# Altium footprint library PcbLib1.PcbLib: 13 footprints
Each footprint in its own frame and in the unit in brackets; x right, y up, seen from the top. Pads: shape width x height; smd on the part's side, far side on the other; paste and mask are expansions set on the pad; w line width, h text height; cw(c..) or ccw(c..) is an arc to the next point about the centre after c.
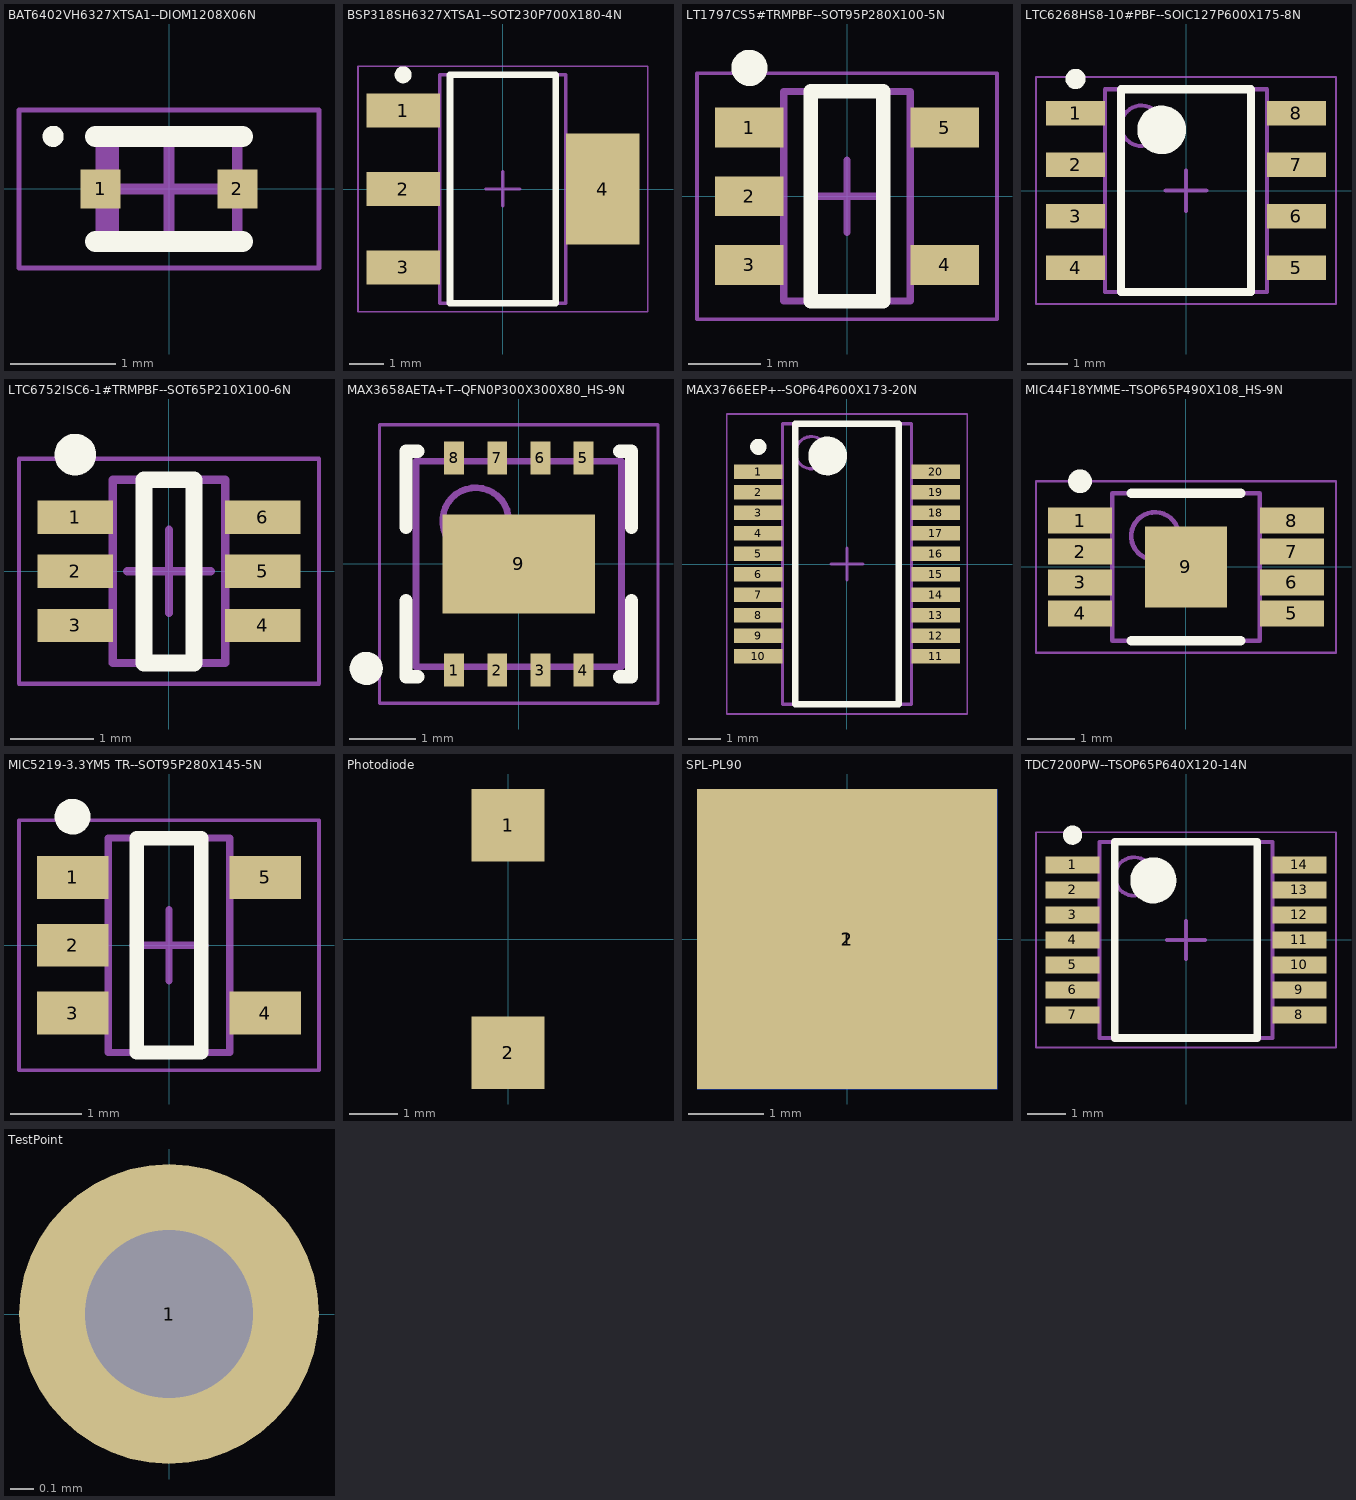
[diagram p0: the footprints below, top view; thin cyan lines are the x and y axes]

## BAT6402VH6327XTSA1--DIOM1208X06N [mm] "Molded Diode, 2-Leads, Body 1.20x0.80mm, IPC Medium Density"
height 0.59
pads (2):
  rect 0.38x0.37 smd: 1(-0.65,0) 2(0.65,0)
Top Overlay:
  circle w0.1: c-1.1,0.5 r0.05
  lines w0.2: -0.7,-0.5 0.7,-0.5 ; -0.7,0.5 0.7,0.5
Mechanical 13:
  rectangle: -0.65,-0.45 -0.475,0.45
  lines w0.1: -0.65,-0.45 0.65,-0.45 0.65,0.45 -0.65,0.45 -0.65,-0.45
Mechanical 15:
  lines w0.05: -1.425,-0.75 1.425,-0.75 1.425,0.75 -1.425,0.75 -1.425,-0.75
  lines w0.1: -0.45,0 0.45,0 ; 0,-0.45 0,0.45
3D body: height 0.59, standoff 0, extent -0.65,-0.45 0.65,0.45

## BSP318SH6327XTSA1--SOT230P700X180-4N [mm] "SOT223, 4-Leads, Body 6.50x7.00mm (avg), Pitch 2.30mm, IPC Medium Density"
height 1.8
pads (4):
  rect 2.15x1 smd: 1(-2.925,2.3) 2(-2.925,0) 3(-2.925,-2.3)
  rect 2.15x3.25 smd: 4(2.925,0)
Top Overlay:
  circle w0.25: c-2.925,3.35 r0.125
  lines w0.2: -1.55,-3.35 1.55,-3.35 1.55,3.35 -1.55,3.35 -1.55,-3.35
Mechanical 13:
  lines w0.1: -1.85,-3.35 1.85,-3.35 1.85,3.35 -1.85,3.35 -1.85,-3.35
Mechanical 15:
  lines w0.05: -4.25,-3.6 4.25,-3.6 4.25,3.6 -4.25,3.6 -4.25,-3.6
  lines w0.1: -0.5,0 0.5,0 ; 0,-0.5 0,0.5
3D body: height 1.8, standoff 0.02, extent -1.85,-3.35 1.85,3.35

## LT1797CS5#TRMPBF--SOT95P280X100-5N [mm] "SOT23, 5-Leads, Body 2.90x2.80mm, Pitch 0.95mm, IPC Medium Density"
height 1
pads (5):
  rect 0.95x0.55 smd: 1(-1.35,0.95) 2(-1.35,0) 3(-1.35,-0.95) 4(1.35,-0.95) 5(1.35,0.95)
Top Overlay:
  circle w0.25: c-1.35,1.775 r0.125
  lines w0.2: -0.5,-1.45 0.5,-1.45 0.5,1.45 -0.5,1.45 -0.5,-1.45
Mechanical 13:
  lines w0.1: -0.875,-1.45 -0.875,1.45 0.875,1.45 0.875,-1.45 -0.875,-1.45
Mechanical 15:
  lines w0.05: -2.075,-1.7 -2.075,1.7 2.075,1.7 2.075,-1.7 -2.075,-1.7
  lines w0.1: -0.5,0 0.5,0 ; 0,-0.5 0,0.5
3D body: height 1, standoff 0, extent -0.875,-1.45 0.875,1.45

## LTC6268HS8-10#PBF--SOIC127P600X175-8N [mm] "SOIC, 8-Leads, Body 4.90x3.90mm, Pitch 1.27mm, IPC Medium Density"
height 1.76
pads (8):
  rect 1.45x0.6 smd: 1(-2.725,1.905) 2(-2.725,0.635) 3(-2.725,-0.635) 4(-2.725,-1.905) 5(2.725,-1.905) 6(2.725,-0.635) 7(2.725,0.635) 8(2.725,1.905)
Top Overlay:
  circle w0.25: c-2.725,2.755 r0.125
  circle w0.6: c-0.6,1.5 r0.3
  lines w0.2: -1.6,-2.5 -1.6,2.5 1.6,2.5 1.6,-2.5 -1.6,-2.5
Mechanical 13:
  circle w0.1: c-1.1,1.6 r0.5
  lines w0.1: -2,-2.5 -2,2.5 2,2.5 2,-2.5 -2,-2.5
Mechanical 15:
  lines w0.05: -3.7,-2.8 -3.7,2.8 3.7,2.8 3.7,-2.8 -3.7,-2.8
  lines w0.1: -0.5,0 0.5,0 ; 0,-0.5 0,0.5
3D body: height 1.76, standoff 0.1, extent -2,-2.5 2,2.5

## LTC6752ISC6-1#TRMPBF--SOT65P210X100-6N [mm] "SOT23, 6-Leads, Body 2.00x2.10mm, Pitch 0.65mm, IPC Medium Density"
height 1
pads (6):
  rect 0.9x0.4 smd: 1(-1.125,0.65) 2(-1.125,0) 3(-1.125,-0.65) 4(1.125,-0.65) 5(1.125,0) 6(1.125,0.65)
Top Overlay:
  circle w0.25: c-1.125,1.4 r0.125
  lines w0.2: -0.3,-1.1 0.3,-1.1 0.3,1.1 -0.3,1.1 -0.3,-1.1
Mechanical 13:
  lines w0.1: -0.675,-1.1 -0.675,1.1 0.675,1.1 0.675,-1.1 -0.675,-1.1
Mechanical 15:
  lines w0.05: -1.8,-1.35 -1.8,1.35 1.8,1.35 1.8,-1.35 -1.8,-1.35
  lines w0.1: -0.5,0 0.5,0 ; 0,-0.5 0,0.5
3D body: height 1, standoff 0, extent -0.675,-1.1 0.675,1.1

## MAX3658AETA+T--QFN0P300X300X80_HS-9N [mm] "QFN, 8-Leads, Body 3.00x3.00mm, Pitch 0.65mm/0.00mm, Thermal Pad 2.30x1.50mm, IPC Medium Density"
height 0.8
pads (9):
  rect 0.3x0.5 smd: 1(-0.975,-1.6) 2(-0.325,-1.6) 3(0.325,-1.6) 4(0.975,-1.6) 5(0.975,1.6) 6(0.325,1.6) 7(-0.325,1.6) 8(-0.975,1.6)
  rect 2.3x1.5 smd: 9(0,0)
Top Overlay:
  circle w0.25: c-2.3,-1.575 r0.125
  lines w0.2: -1.7,-0.55 -1.7,-1.7 -1.525,-1.7 ; -1.7,0.55 -1.7,1.7 -1.525,1.7 ; 1.525,-1.7 1.7,-1.7 1.7,-0.55 ; 1.525,1.7 1.7,1.7 1.7,0.55
Mechanical 13:
  circle w0.1: c-0.65,0.65 r0.5
  lines w0.1: -1.55,-1.55 1.55,-1.55 1.55,1.55 -1.55,1.55 -1.55,-1.55
Mechanical 15:
  lines w0.05: -2.1,-2.1 2.1,-2.1 2.1,2.1 -2.1,2.1 -2.1,-2.1
  lines w0.1: -0.5,0 0.5,0 ; 0,-0.5 0,0.5
3D body: height 0.8, standoff 0, extent -1.55,-1.55 1.55,1.55

## MAX3766EEP+--SOP64P600X173-20N [mm] "SOP, 20-Leads, Body 8.65x3.90mm, Pitch 0.64mm, IPC Medium Density"
height 1.73
pads (20):
  rect 1.5x0.45 smd: 1(-2.75,2.857) 2(-2.75,2.222) 3(-2.75,1.587) 4(-2.75,0.953) 5(-2.75,0.318) 6(-2.75,-0.318) 7(-2.75,-0.953) 8(-2.75,-1.587) 9(-2.75,-2.222) 10(-2.75,-2.857) 11(2.75,-2.857) 12(2.75,-2.222) 13(2.75,-1.587) 14(2.75,-0.953) 15(2.75,-0.318) 16(2.75,0.318) 17(2.75,0.953) 18(2.75,1.587) 19(2.75,2.222) 20(2.75,2.857)
Top Overlay:
  circle w0.6: c-0.6,3.35 r0.3
  circle w0.25: c-2.75,3.632 r0.125
  lines w0.2: -1.6,-4.35 1.6,-4.35 1.6,4.35 -1.6,4.35 -1.6,-4.35
Mechanical 13:
  circle w0.1: c-1.1,3.45 r0.5
  lines w0.1: -2,-4.35 2,-4.35 2,4.35 -2,4.35 -2,-4.35
Mechanical 15:
  lines w0.05: -3.725,-4.65 3.725,-4.65 3.725,4.65 -3.725,4.65 -3.725,-4.65
  lines w0.1: -0.5,0 0.5,0 ; 0,-0.5 0,0.5
3D body: height 1.73, standoff 0.1, extent -2,-4.35 2,4.35

## MIC44F18YMME--TSOP65P490X108_HS-9N [mm] "TSOP, 8-Leads, Body 3.00x3.00mm, Pitch 0.65mm, Thermal Pad 1.70x1.73mm, IPC Medium Density"
height 1.08
pads (9):
  rect 1.35x0.55 smd: 1(-2.225,0.975) 2(-2.225,0.325) 3(-2.225,-0.325) 4(-2.225,-0.975) 5(2.225,-0.975) 6(2.225,-0.325) 7(2.225,0.325) 8(2.225,0.975)
  rect 1.73x1.7 smd: 9(0,0)
Top Overlay:
  circle w0.25: c-2.225,1.8 r0.125
  lines w0.2: -1.15,-1.55 1.15,-1.55 ; -1.15,1.55 1.15,1.55
Mechanical 13:
  circle w0.1: c-0.65,0.65 r0.5
  lines w0.1: -1.55,-1.55 -1.55,1.55 1.55,1.55 1.55,-1.55 -1.55,-1.55
Mechanical 15:
  lines w0.05: -3.15,-1.8 -3.15,1.8 3.15,1.8 3.15,-1.8 -3.15,-1.8
  lines w0.1: -0.5,0 0.5,0 ; 0,-0.5 0,0.5
3D body: height 1.08, standoff 0.05, extent -1.55,-1.55 1.55,1.55

## MIC5219-3.3YM5 TR--SOT95P280X145-5N [mm] "SOT23, 5-Leads, Body 2.90x2.80mm, Pitch 0.95mm, IPC Medium Density"
height 1.45
pads (5):
  rect 1x0.6 smd: 1(-1.35,0.95) 2(-1.35,0) 3(-1.35,-0.95) 4(1.35,-0.95) 5(1.35,0.95)
Top Overlay:
  circle w0.25: c-1.35,1.8 r0.125
  lines w0.2: -0.45,-1.5 -0.45,1.5 0.45,1.5 0.45,-1.5 -0.45,-1.5
Mechanical 13:
  lines w0.1: -0.85,-1.5 0.85,-1.5 0.85,1.5 -0.85,1.5 -0.85,-1.5
Mechanical 15:
  lines w0.05: -2.1,-1.75 2.1,-1.75 2.1,1.75 -2.1,1.75 -2.1,-1.75
  lines w0.1: -0.5,0 0.5,0 ; 0,-0.5 0,0.5
3D body: height 1.45, standoff 0, extent -0.85,-1.5 0.85,1.5

## Photodiode [mm]
pads (2):
  rect 1.5x1.5 smd: 1(0,2.35) 2(0,-2.35)

## SPL-PL90 [mm]
pads (2):
  rect 4x4 smd far side: 1(0,0)
  rect 4x4 smd: 2(0,0)

## TDC7200PW--TSOP65P640X120-14N [mm] "TSOP, 14-Leads, Body 5.00x4.40mm, Pitch 0.65mm, IPC Medium Density"
height 1.2
pads (14):
  rect 1.4x0.45 smd: 1(-2.95,1.95) 2(-2.95,1.3) 3(-2.95,0.65) 4(-2.95,0) 5(-2.95,-0.65) 6(-2.95,-1.3) 7(-2.95,-1.95) 8(2.95,-1.95) 9(2.95,-1.3) 10(2.95,-0.65) 11(2.95,0) 12(2.95,0.65) 13(2.95,1.3) 14(2.95,1.95)
Top Overlay:
  circle w0.6: c-0.85,1.55 r0.3
  circle w0.25: c-2.95,2.725 r0.125
  lines w0.2: -1.85,-2.55 1.85,-2.55 1.85,2.55 -1.85,2.55 -1.85,-2.55
Mechanical 13:
  circle w0.1: c-1.35,1.65 r0.5
  lines w0.1: -2.25,-2.55 2.25,-2.55 2.25,2.55 -2.25,2.55 -2.25,-2.55
Mechanical 15:
  lines w0.05: -3.9,-2.8 3.9,-2.8 3.9,2.8 -3.9,2.8 -3.9,-2.8
  lines w0.1: -0.5,0 0.5,0 ; 0,-0.5 0,0.5
3D body: height 1.2, standoff 0.05, extent -2.25,-2.55 2.25,2.55

## TestPoint [mil]
pads (1):
  round 50 hole 28: 1(0,0)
